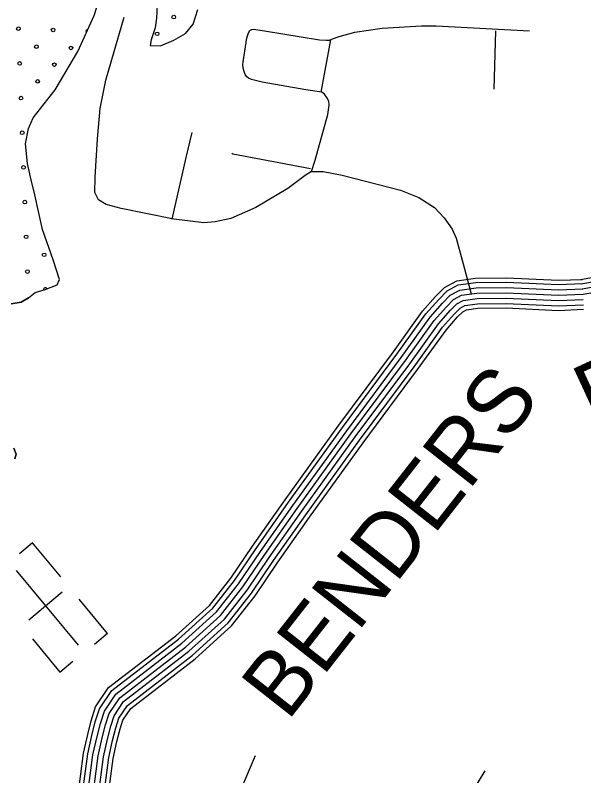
# Model space of a CAD drawing. Extents: x 1788175 to 1969470, y 584502 to 738744.
# Drawn here: x 1821086 to 1824393, y 713422 to 717843 of the extents above; entities that cross this region are included whole.
import ezdxf

# ---------------------------------------------------------------- set-up
doc = ezdxf.new("R2010")
doc.units = 0
for name, color, linetype in [('DESIGN - ROW - Right-of-Way and Easement Labels', 7, 'Continuous'), ('DESIGN - SCRATCH - User 1', 7, 'Continuous'), ('DESIGN - TRAFFIC CONTROL PERMANENT - Pavement Marking Text', 7, 'Continuous'), ('DESIGN - TRANSPORTATION - Edge of Traveled Way', 7, 'Continuous'), ('DESIGN - UTILITIES - Cable (Underground) with Text', 7, 'Continuous'), ('SURVEY - TRANSPORTATION - Roads', 7, 'Continuous')]:
    doc.layers.add(name, color=color, linetype=linetype)

msp = doc.modelspace()

# ---------------------------------------------------------------- linework, layer by layer
at = {"layer": 'DESIGN - SCRATCH - User 1'}
for points in [[(1821163.3, 716199.6), (1821202.2, 716231.8), (1821260.5, 716249), (1821329, 716276), (1821343.4, 716305.8), (1821307.2, 716420.5), (1821243.9, 716597.7), (1821221.6, 716702.2), (1821199.1, 716798.7), (1821178.4, 716885.1), (1821157.9, 716981.5), (1821145.7, 717095.9), (1821163, 717183.7), (1821190, 717245.4), (1821318.7, 717409.7), (1821450.2, 717632.1), (1821545.6, 717841), (1821610.9, 718048.3)], [(1821910.8, 717903.7), (1821907.6, 717825.7), (1821898.7, 717769.7), (1821875.6, 717699.9), (1821871.1, 717666), (1821931.1, 717665.1), (1822007.6, 717698), (1822076.3, 717737), (1822121.2, 717790.5), (1822148.5, 717876.2)], [(1821062.5, 716165.9), (1821120.7, 716174.6), (1821163.3, 716199.6)], [(1821082.7, 715263.8), (1821091.3, 715291.6), (1821078.2, 715326)]]:
    msp.add_lwpolyline(points, dxfattribs=at)
at = {"layer": 'DESIGN - TRAFFIC CONTROL PERMANENT - Pavement Marking Text'}
for centre in [(1822007.7, 717831.4), (1821104.2, 717764.2), (1821305.8, 717756.8), (1821910.6, 717734.4), (1821208.7, 717659.7), (1821410.3, 717652.2), (1821111.6, 717562.6), (1821313.2, 717555.2), (1821216.2, 717458.1), (1821119.1, 717361), (1821126.6, 717159.4), (1821134, 716957.8), (1821141.5, 716756.2), (1821149, 716554.6), (1821253.5, 716450), (1821156.4, 716353)]:
    msp.add_circle(centre, 10.6, dxfattribs=at)
for centre, start, end in [((1821507.4, 717749.3), 83.8845, 227.0538), ((1821261, 716248.4), 25.3287, 192.7554)]:
    msp.add_arc(centre, 10.6, start, end, dxfattribs=at)
at = {"layer": 'DESIGN - TRANSPORTATION - Edge of Traveled Way'}
for points in [[(1821163.3, 716199.6), (1821202.2, 716231.8), (1821260.5, 716249), (1821329, 716276), (1821343.4, 716305.8), (1821307.2, 716420.5), (1821243.9, 716597.7), (1821221.6, 716702.2), (1821199.1, 716798.7), (1821178.4, 716885.1), (1821157.9, 716981.5), (1821145.7, 717095.9), (1821163, 717183.7), (1821190, 717245.4), (1821318.7, 717409.7), (1821450.2, 717632.1), (1821545.6, 717841), (1821610.9, 718048.3)], [(1821910.8, 717903.7), (1821907.6, 717825.7), (1821898.7, 717769.7), (1821875.6, 717699.9), (1821871.1, 717666), (1821931.1, 717665.1), (1822007.6, 717698), (1822076.3, 717737), (1822121.2, 717790.5), (1822148.5, 717876.2)], [(1821163.3, 716199.6), (1821120.7, 716174.6), (1821062.5, 716165.9)], [(1821078.2, 715326), (1821091.3, 715291.6), (1821082.7, 715263.8)]]:
    msp.add_lwpolyline(points, dxfattribs=at)
at = {"layer": 'DESIGN - UTILITIES - Cable (Underground) with Text'}
for p, q in [((1821186.5, 714775.5), (1821109.7, 714711.8)), ((1821350.3, 714577.8), (1821186.5, 714775.4)), ((1821359.3, 714488.6), (1821164.1, 714326.7)), ((1821622.5, 714249.5), (1821457.8, 714448.2)), ((1821622.4, 714249.4), (1821545.8, 714185.8)), ((1821185.3, 714218.7), (1821345.8, 714025.1)), ((1821345.9, 714025.2), (1821421.5, 714087.9))]:
    msp.add_line(p, q, dxfattribs=at)
msp.add_lwpolyline([(1821092, 714614.7), (1821451.3, 714181.3)], dxfattribs=at)
at = {"layer": 'SURVEY - TRANSPORTATION - Roads'}
for points in [[(1822808.3, 716935.1), (1822771.9, 716911.6), (1822670.6, 716835), (1822484.8, 716725.6), (1822339.7, 716661.7), (1822249.3, 716641), (1822183.2, 716635.9), (1822007.4, 716656.6), (1821702.1, 716719.1), (1821614.4, 716742.5), (1821570.8, 716769.1), (1821549.5, 716811.5), (1821551.2, 716900.4), (1821563.3, 717124.1), (1821579.1, 717299.8), (1821611.7, 717465.5), (1821719.5, 717830.4)], [(1822410.9, 717570.8), (1822428.1, 717683.6), (1822431.2, 717701.9), (1822436.6, 717723.5), (1822443.4, 717740.4), (1822451, 717753.6), (1822461.7, 717760.2), (1822470.9, 717760.8), (1822535.6, 717751.1), (1822855, 717700.3), (1822895, 717697.7), (1822911, 717697.3), (1822931.5, 717704.6), (1822969.4, 717718.7), (1823061.8, 717743.3), (1823220.3, 717767), (1823448.7, 717781.7), (1823533.2, 717780.4), (1824077.2, 717752.4)], [(1823879.8, 717752.4), (1823869.4, 717413.1)], [(1822918.6, 717700), (1822862.9, 717395.8)], [(1822808.3, 716935.1), (1822829.3, 717000.9), (1822903.5, 717266.2), (1822912.3, 717320.2), (1822908.9, 717342.1), (1822898.1, 717363.7), (1822883.7, 717383), (1822869.5, 717394.9), (1822775.6, 717408.3), (1822522.2, 717454.1), (1822460.4, 717469), (1822455.6, 717471.1), (1822442.9, 717477.1), (1822432.6, 717485.4), (1822423.1, 717497.5), (1822417.1, 717515.7), (1822411.7, 717535.4), (1822409.7, 717555.9), (1822410.9, 717570.8)], [(1821999.3, 716658.2), (1822079, 717016), (1822115.2, 717161.7)], [(1824372.9, 716306.2), (1824555.8, 716338.9), (1824677.6, 716371.8), (1824797.8, 716417.4), (1824947.4, 716499.7), (1825268.7, 716730), (1825560.1, 716943.4), (1825709.6, 717039.3), (1825806.3, 717087.9), (1825886.2, 717128.5), (1825962.1, 717159), (1826004.8, 717164.9), (1826060.2, 717160.5), (1826123, 717118.1), (1826160.6, 717095.2), (1826168.4, 717091.6), (1826171.4, 717090.8), (1826273.2, 717093), (1826556.6, 717076.5), (1826741.3, 717048.8), (1827183.8, 716949.3), (1827502.3, 716872.2), (1827544.3, 716861.1)], [(1824377.2, 716281.9), (1824561.2, 716314.7), (1824685.2, 716348.3), (1824808.2, 716394.9), (1824960.6, 716478.8), (1825283.2, 716710), (1825574, 716923), (1825721.9, 717017.8), (1825817.5, 717065.9), (1825896.5, 717106), (1825968.5, 717134.9), (1826005.6, 717140), (1826051.7, 717136.4), (1826109.7, 717097.3), (1826149, 717073.3), (1826160.2, 717068.2), (1826168.6, 717066), (1826272.8, 717068.3), (1826554, 717051.9), (1826736.7, 717024.5), (1827178.1, 716925.3), (1827496.3, 716848.2), (1827536, 716837.8)], [(1824382.7, 716251.4), (1824568, 716284.5), (1824694.8, 716318.8), (1824821.2, 716366.7), (1824977.2, 716452.5), (1825301.4, 716684.9), (1825591.6, 716897.4), (1825737.3, 716990.8), (1825831.5, 717038.2), (1825909.3, 717077.7), (1825976.5, 717104.7), (1826006.5, 717108.9), (1826041.2, 717106.2), (1826092.9, 717071.3), (1826134.4, 717045.9), (1826149.8, 717038.8), (1826165.1, 717034.9), (1826272.2, 717037.3), (1826550.8, 717021), (1826731, 716994), (1827171.1, 716895.1), (1827488.7, 716818.2), (1827525.5, 716808.5)], [(1824388.1, 716220.9), (1824574.8, 716254.2), (1824704.4, 716289.2), (1824834.3, 716338.5), (1824993.7, 716426.2), (1825319.6, 716659.8), (1825609.1, 716871.8), (1825752.7, 716963.8), (1825845.4, 717010.5), (1825922.1, 717049.4), (1825984.5, 717074.6), (1826007.4, 717077.7), (1826030.6, 717075.9), (1826076.1, 717045.2), (1826119.8, 717018.5), (1826139.4, 717009.5), (1826161.6, 717003.9), (1826271.7, 717006.2), (1826547.6, 716990.2), (1826725.3, 716963.5), (1827164.1, 716864.9), (1827481.1, 716788.1), (1827515.1, 716779.1)], [(1824388.1, 716220.9), (1824574.8, 716254.2), (1824704.4, 716289.2), (1824834.3, 716338.5), (1824993.7, 716426.2), (1825319.6, 716659.8), (1825609.1, 716871.8), (1825752.7, 716963.8), (1825845.4, 717010.5), (1825922.1, 717049.4), (1825984.5, 717074.6), (1826007.4, 717077.7), (1826030.6, 717075.9), (1826076.1, 717045.2), (1826119.8, 717018.5), (1826139.4, 717009.5), (1826161.6, 717003.9), (1826271.7, 717006.2), (1826547.6, 716990.2), (1826725.3, 716963.5), (1827164.1, 716864.9), (1827481.1, 716788.1), (1827558.4, 716767.7)], [(1822346.3, 717039.9), (1822351.8, 717037.3), (1822618.8, 716986.8)], [(1822618.8, 716986.8), (1822802.2, 716952.3)], [(1822808.3, 716935.1), (1822876.3, 716934.1), (1822988, 716912.5), (1823326.9, 716825.4), (1823432.3, 716783.7), (1823523.4, 716724.3), (1823580.6, 716665.4), (1823626.9, 716598.3), (1823650.7, 716546.2), (1823690.4, 716397.4), (1823738, 716223.4)], [(1821429.9, 713147.1), (1821482.9, 713553.9), (1821507.7, 713662.7), (1821527.8, 713742.1), (1821553.4, 713822.3), (1821629.1, 713934.6), (1822019.6, 714236), (1822216, 714412.8), (1822340.1, 714570.7), (1822465.8, 714757.2), (1822654.9, 715025.9), (1822968.6, 715460.9), (1823285.5, 715886.8), (1823455.3, 716121.6), (1823530.9, 716207.5), (1823582.3, 716259.9), (1823653.7, 716298.9), (1823763.3, 716314.7), (1823943.7, 716316.2), (1824246.2, 716301.8), (1824384.5, 716307.5)], [(1821454.5, 713144.2), (1821507.2, 713549.6), (1821531.7, 713656.9), (1821551.5, 713735.3), (1821575.9, 713811.4), (1821647.4, 713917.4), (1822035.4, 714217), (1822234.1, 714395.8), (1822360.1, 714556.2), (1822486.2, 714743.2), (1822675.1, 715011.6), (1822988.5, 715446.3), (1823305.4, 715872.2), (1823474.7, 716106.1), (1823549, 716190.7), (1823597.4, 716239.9), (1823661.7, 716275.1), (1823765.1, 716290), (1823943.2, 716291.5), (1824246.1, 716277), (1824385.6, 716282.8)], [(1821485.2, 713140.5), (1821537.8, 713544.1), (1821561.8, 713649.7), (1821581.4, 713726.8), (1821604, 713797.7), (1821670.3, 713896), (1822055.3, 714193.2), (1822256.8, 714374.6), (1822385.2, 714537.9), (1822511.7, 714725.6), (1822700.3, 714993.6), (1823013.6, 715427.9), (1823330.4, 715853.9), (1823498.9, 716086.8), (1823571.8, 716169.6), (1823616.3, 716214.9), (1823671.6, 716245.2), (1823767.5, 716259), (1823942.6, 716260.5), (1824246, 716246), (1824386.8, 716251.9)], [(1821516, 713136.9), (1821568.3, 713538.6), (1821592, 713642.4), (1821611.2, 713718.3), (1821632.2, 713784.1), (1821693.2, 713874.5), (1822075.2, 714169.4), (1822279.5, 714353.3), (1822410.2, 714519.6), (1822537.3, 714708), (1822725.6, 714975.6), (1823038.6, 715409.6), (1823355.4, 715835.5), (1823523.2, 716067.4), (1823594.5, 716148.5), (1823635.2, 716189.9), (1823681.6, 716215.3), (1823769.8, 716228), (1823942, 716229.5), (1824245.9, 716215), (1824388.1, 716220.9)], [(1821516, 713136.9), (1821568.3, 713538.6), (1821592, 713642.4), (1821611.2, 713718.3), (1821632.2, 713784.1), (1821693.2, 713874.5), (1822075.2, 714169.4), (1822279.5, 714353.3), (1822410.2, 714519.6), (1822537.3, 714708), (1822725.6, 714975.6), (1823038.6, 715409.6), (1823355.4, 715835.5), (1823523.2, 716067.4), (1823594.5, 716148.5), (1823635.2, 716189.9), (1823681.6, 716215.3), (1823769.8, 716228), (1823942, 716229.5), (1824245.9, 716215), (1824388.1, 716220.9)], [(1821546.8, 713133.2), (1821598.9, 713533.2), (1821622.1, 713635.2), (1821641, 713709.7), (1821660.4, 713770.4), (1821716.1, 713853), (1822095, 714145.5), (1822302.3, 714332.1), (1822435.3, 714501.4), (1822562.8, 714690.4), (1822750.8, 714957.6), (1823063.6, 715391.3), (1823380.4, 715817.2), (1823547.4, 716048), (1823617.2, 716127.4), (1823654.1, 716164.9), (1823691.5, 716185.4), (1823772.2, 716197), (1823941.4, 716198.5), (1824245.9, 716183.9), (1824389.4, 716189.9)], [(1821577.6, 713129.5), (1821629.4, 713527.7), (1821652.3, 713628), (1821670.8, 713701.2), (1821688.6, 713756.7), (1821739, 713831.5), (1822114.9, 714121.7), (1822325, 714310.8), (1822460.4, 714483.1), (1822588.3, 714672.8), (1822776.1, 714939.6), (1823088.6, 715373), (1823405.4, 715798.9), (1823571.7, 716028.7), (1823639.9, 716106.2), (1823673, 716139.9), (1823701.5, 716155.5), (1823774.6, 716166), (1823940.8, 716167.4), (1824245.8, 716152.9), (1824390.7, 716158.9)], [(1821603.1, 713126.5), (1821654.8, 713523.2), (1821677.3, 713621.9), (1821695.5, 713694.1), (1821711.9, 713745.4), (1821758, 713813.7), (1822131.4, 714102), (1822343.8, 714293.2), (1822481.2, 714467.9), (1822609.5, 714658.2), (1822797, 714924.7), (1823109.3, 715357.8), (1823426.2, 715783.7), (1823591.8, 716012.6), (1823658.8, 716088.7), (1823688.6, 716119.2), (1823709.8, 716130.7), (1823776.5, 716140.3), (1823940.3, 716141.7), (1824245.7, 716127.2), (1824391.8, 716133.2)], [(1822319.1, 713154.1), (1822484.1, 713539.1)], [(1823564.2, 712831.8), (1823605.9, 712890.2), (1823630.9, 712952.8), (1823643.4, 713003), (1823643.4, 713094.8), (1823643.4, 713149.1), (1823664.2, 713195), (1823819.1, 713450.5)]]:
    msp.add_lwpolyline(points, dxfattribs=at)

# ---------------------------------------------------------------- texts
at = {"layer": 'DESIGN - ROW - Right-of-Way and Easement Labels'}
for s, rotation, p in [('FERRY', 24.8284, (1824452.4, 715436.2)), ('BENDERS', 51.867, (1822669.9, 713734.5))]:
    msp.add_text(s, height=370, rotation=rotation, dxfattribs=at).set_placement(p)

doc.saveas('drawing.dxf')
